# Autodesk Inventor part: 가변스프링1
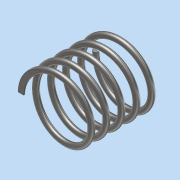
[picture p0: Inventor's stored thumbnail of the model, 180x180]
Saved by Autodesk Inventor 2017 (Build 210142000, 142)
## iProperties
Part Number: 가변스프링1
Material: 강철, 연강
Document SubType Name: Modeling
Designer: MRC
Density: 7.85 g/cm^3
Appearance: 반연마
Mass: 8.38336 g
Surface Area: 21.6556 cm^2
Volume: 1.06794 cm^3
Author: MRC
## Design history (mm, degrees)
sketch "스케치1"
  geometry: L1 (0, 0)-(0, 26.358); L2 (0, 0)-(-11, 0); L3 (0, 26.358)-(-11, 26.358); C1 r 1 at (-11, 0)
  constraints: 6 end point, 2 horizontal, 1 centre point, 1 coincident, 1 vertical
  dimensions: "d0" = 26.35829 distance of L1.start L1.end (derived); "d11" = 11 distance of L1.start L2.end; "d12" = 2 diameter of C1
feature "코일1" sketch "스케치1" pitch "d3" = 10; turns "d5" = 5; dims "d4" = 26.35829 (= d0), "d6" = 0, angle "d7" = 90 deg, angle "d8" = 90 deg, "d9" = 0, "d10" = 0
sketch "스케치2"
  geometry: L1 (26.358, 17.5)-(0, 17.5); L2 (0, 17.5)-(0, -17.5); L3 (0, -17.5)-(26.358, -17.5); L4 (26.358, -17.5)-(26.358, 17.5); 2 further points
  constraints: 8 end point, 2 parallel, 1 coincident, 1 horizontal, 1 midpoint, 1 perpendicular
  dimensions: "d13" = 26.35829 distance of L2.end L3.end (= d0); "d14" = 35 distance of L3.end L1.start
extrude "돌출1" sketch "스케치2" stored distance "d15" = 10; taper "d16" = 0 deg
node "솔리드1"
